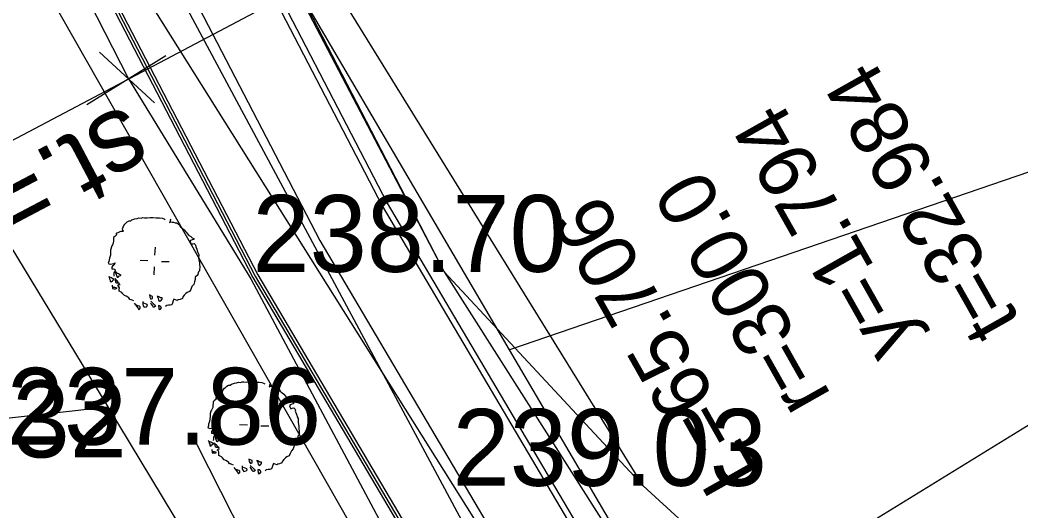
# Model space of a CAD drawing. Extents: x -601754 to -601440, y -1201912 to -1200862.
# Drawn here: x -601544.58 to -601518.53, y -1201354.54 to -1201341.75 of the extents above; entities that cross this region are included whole.
import ezdxf

# ---------------------------------------------------------------- set-up
doc = ezdxf.new("R2010")
doc.units = 0
for name, color, linetype in [('Hranice parcel', 7, 'Continuous'), ('u_drén', 7, 'Continuous'), ('u_hrany', 7, 'Continuous'), ('u_krizky', 7, 'Continuous'), ('u_návrh', 7, 'Continuous'), ('u_oblouky', 7, 'Continuous'), ('u_osa', 7, 'Continuous'), ('u_pricne_cesta', 7, 'Continuous'), ('u_terénní úpravy', 7, 'Continuous'), ('u_vysadba_SO_101', 7, 'Continuous'), ('u_vyska', 7, 'Continuous')]:
    doc.layers.add(name, color=color, linetype=linetype)

msp = doc.modelspace()

# ---------------------------------------------------------------- linework, layer by layer
at = {"layer": 'Hranice parcel'}
for p, q in [((-601697.78, -1201369.54), (-601542.3, -1201351.82)), ((-601542.3, -1201351.82), (-601532.14, -1201368.61))]:
    msp.add_line(p, q, dxfattribs=at)
for points in [[(-601531.84, -1201350.34), (-601539.52, -1201337.25), (-601549.44, -1201315.65)], [(-601555.49, -1201328.67), (-601550, -1201339.12), (-601542.3, -1201351.82)], [(-601508.86, -1201342.47), (-601512.53, -1201343.73), (-601531.84, -1201350.34)], [(-601514.66, -1201382.62), (-601516.09, -1201378.41), (-601518.22, -1201373.55), (-601531.84, -1201350.34)]]:
    msp.add_lwpolyline(points, dxfattribs=at)
at = {"layer": 'u_drén'}
msp.add_lwpolyline([(-601553.194, -1201317.864), (-601552.875, -1201318.687), (-601546.074, -1201333.752), (-601538.46, -1201348.424), (-601530.069, -1201362.635), (-601525.78, -1201369.465), (-601523.226, -1201373.891), (-601521.024, -1201378.462), (-601519.169, -1201383.184), (-601517.66, -1201388.066), (-601516.532, -1201392.263), (-601515.324, -1201397.601), (-601514.551, -1201402.98), (-601514.21, -1201408.403), (-601514.303, -1201413.875), (-601516.032, -1201444.23), (-601516.195, -1201450.215), (-601516.005, -1201456.227), (-601515.463, -1201462.19), (-601510.248, -1201505.371), (-601509.825, -1201509.657), (-601509.591, -1201513.936), (-601509.544, -1201518.242), (-601509.788, -1201540.615)], dxfattribs=at)
at = {"layer": 'u_hrany'}
for points in [[(-601564.55, -1201274.22), (-601554.98, -1201301.75), (-601550.1, -1201315.28), (-601544.95, -1201324.64), (-601539.81, -1201336.34), (-601533.54, -1201348.31)], [(-601563.01, -1201293.69), (-601544.18, -1201340.47), (-601528.42, -1201368.16), (-601520.9, -1201374.92)], [(-601528.36, -1201353.88), (-601539.51, -1201335.83), (-601544.47, -1201324.44)], [(-601520.9, -1201374.92), (-601531.36, -1201358), (-601541.87, -1201338.39)], [(-601533.54, -1201348.31), (-601528.36, -1201353.88), (-601525.06, -1201356.91)], [(-601520.9, -1201374.92), (-601531.08, -1201370.35), (-601539.97, -1201352.81)]]:
    msp.add_lwpolyline(points, dxfattribs=at)
at = {"layer": 'u_krizky'}
for p, q in [((-601540.791, -1201342.686), (-601542.843, -1201343.966)), ((-601541.084, -1201343.913), (-601542.51, -1201342.593))]:
    msp.add_line(p, q, dxfattribs=at)
at = {"layer": 'u_návrh'}
for points in [[(-601563.542, -1201278.368), (-601555.153, -1201301.929), (-601549.253, -1201317.17), (-601542.541, -1201332.04), (-601535.025, -1201346.521), (-601526.716, -1201360.593), (-601522.417, -1201367.44), (-601519.753, -1201372.056), (-601517.425, -1201376.89), (-601515.462, -1201381.885), (-601513.889, -1201386.977), (-601512.721, -1201391.321), (-601511.461, -1201396.888), (-601510.644, -1201402.577), (-601510.283, -1201408.313), (-601510.38, -1201414.02), (-601512.11, -1201444.395)], [(-601567.28, -1201279.795), (-601558.903, -1201303.323), (-601552.944, -1201318.716), (-601546.141, -1201333.785), (-601538.525, -1201348.46), (-601530.133, -1201362.674), (-601525.844, -1201369.504), (-601523.292, -1201373.926), (-601521.093, -1201378.492), (-601519.24, -1201383.209), (-601517.732, -1201388.087), (-601516.605, -1201392.281), (-601515.398, -1201397.615), (-601514.626, -1201402.988), (-601514.285, -1201408.405), (-601514.378, -1201413.873), (-601516.107, -1201444.227)], [(-601549.753, -1201316.295), (-601549.392, -1201317.228), (-601542.676, -1201332.105), (-601535.157, -1201346.594), (-601526.844, -1201360.671), (-601522.546, -1201367.518), (-601519.886, -1201372.126), (-601517.562, -1201376.951), (-601515.604, -1201381.935), (-601514.033, -1201387.018), (-601512.867, -1201391.357), (-601511.609, -1201396.915), (-601510.793, -1201402.592), (-601510.433, -1201408.317), (-601510.53, -1201414.015), (-601512.26, -1201444.389), (-601512.419, -1201450.207), (-601512.236, -1201455.996), (-601511.709, -1201461.793), (-601506.495, -1201504.959), (-601506.06, -1201509.368), (-601505.817, -1201513.812), (-601505.769, -1201518.242), (-601506.187, -1201556.503)], [(-601553.136, -1201317.803), (-601552.806, -1201318.658), (-601546.006, -1201333.72), (-601538.394, -1201348.388), (-601530.005, -1201362.596), (-601525.716, -1201369.427), (-601523.16, -1201373.856), (-601520.956, -1201378.432), (-601519.098, -1201383.159), (-601517.588, -1201388.045), (-601516.46, -1201392.245), (-601515.25, -1201397.587), (-601514.477, -1201402.972), (-601514.135, -1201408.402), (-601514.228, -1201413.878), (-601515.957, -1201444.233), (-601516.12, -1201450.215), (-601515.93, -1201456.223), (-601515.388, -1201462.182), (-601510.174, -1201505.363), (-601509.75, -1201509.651), (-601509.516, -1201513.934), (-601509.469, -1201518.242), (-601509.714, -1201540.624)]]:
    msp.add_lwpolyline(points, dxfattribs=at)
at = {"layer": 'u_oblouky'}
msp.add_line((-601528.425, -1201361.634), (-601545.965, -1201333.7), dxfattribs=at)
at = {"layer": 'u_osa'}
msp.add_lwpolyline([(-601557.028, -1201302.626), (-601551.099, -1201317.943), (-601544.341, -1201332.912), (-601536.775, -1201347.491), (-601528.425, -1201361.634), (-601524.131, -1201368.472), (-601521.523, -1201372.991), (-601519.259, -1201377.691), (-601517.351, -1201382.547), (-601515.811, -1201387.532), (-601514.663, -1201391.801), (-601513.43, -1201397.251), (-601512.635, -1201402.782), (-601512.284, -1201408.359), (-601512.379, -1201413.946), (-601514.108, -1201444.311)], dxfattribs=at)
at = {"layer": 'u_pricne_cesta'}
for points in [[(-601521.874, -1201332.787), (-601539.559, -1201342.128), (-601557.243, -1201351.468)], [(-601512.743, -1201348.863), (-601529.774, -1201359.348), (-601546.805, -1201369.834)]]:
    msp.add_lwpolyline(points, dxfattribs=at)
at = {"layer": 'u_terénní úpravy'}
for points in [[(-601563.549, -1201276.755), (-601560.467, -1201285.585), (-601555.466, -1201299.915), (-601555, -1201301.25), (-601553.702, -1201304.613), (-601549.711, -1201315.986), (-601546.008, -1201323.122), (-601539.52, -1201337.25), (-601537.344, -1201340.958), (-601533.54, -1201348.31), (-601527.44, -1201357.911), (-601522.351, -1201366.758), (-601519.36, -1201371.808), (-601517.434, -1201375.343), (-601516.299, -1201378.722), (-601515.181, -1201381.785), (-601513.502, -1201386.766), (-601512.274, -1201391.071), (-601511.36, -1201394.458), (-601510.891, -1201396.937), (-601510.105, -1201401.304), (-601509.884, -1201408.41), (-601509.865, -1201414.917), (-601511.161, -1201434.926)], [(-601565.037, -1201287.212), (-601558.145, -1201306.245), (-601553.368, -1201318.894), (-601550.549, -1201325.146), (-601546.519, -1201333.968), (-601541.758, -1201343.289), (-601538.578, -1201348.49), (-601532.041, -1201360.744), (-601526.088, -1201369.629), (-601523.664, -1201374.122), (-601522.125, -1201377.501), (-601519.788, -1201383.401), (-601518.29, -1201388.248), (-601517.27, -1201392.04), (-601516.455, -1201395.572), (-601515.96, -1201398.024), (-601515.065, -1201403.029), (-601514.933, -1201414.628), (-601514.933, -1201414.628), (-601516.331, -1201434.631)]]:
    msp.add_lwpolyline(points, dxfattribs=at)
at = {"layer": 'u_vysadba_SO_101'}
for points in [[(-601542.07, -1201347.331), (-601542.069, -1201347.302), (-601542.009, -1201347.276), (-601541.979, -1201347.263), (-601541.949, -1201347.25), (-601541.92, -1201347.251), (-601541.89, -1201347.253), (-601541.903, -1201347.223), (-601541.916, -1201347.193), (-601541.9, -1201347.15), (-601541.883, -1201347.107), (-601541.851, -1201347.065), (-601541.82, -1201347.037), (-601541.79, -1201347.009), (-601541.744, -1201346.983), (-601541.7, -1201346.985), (-601541.67, -1201346.957), (-601541.595, -1201346.932), (-601541.536, -1201346.92), (-601541.491, -1201346.908), (-601541.433, -1201346.911), (-601541.388, -1201346.899), (-601541.345, -1201346.901), (-601541.272, -1201346.905), (-601541.198, -1201346.894), (-601541.125, -1201346.898), (-601541.037, -1201346.903), (-601540.95, -1201346.907), (-601540.877, -1201346.911), (-601540.834, -1201346.928), (-601540.805, -1201346.944)], [(-601540.658, -1201346.937), (-601540.674, -1201346.966), (-601540.676, -1201346.995), (-601540.692, -1201347.023), (-601540.648, -1201347.011), (-601540.618, -1201347.013), (-601540.589, -1201347.014), (-601540.546, -1201347.031), (-601540.502, -1201347.033), (-601540.46, -1201347.065), (-601540.432, -1201347.096), (-601540.406, -1201347.141), (-601540.363, -1201347.173), (-601540.307, -1201347.22), (-601540.266, -1201347.266), (-601540.238, -1201347.296), (-601540.197, -1201347.357), (-601540.14, -1201347.389), (-601540.098, -1201347.421), (-601540.055, -1201347.438), (-601540.057, -1201347.467)], [(-601542.07, -1201347.331), (-601542.071, -1201347.346), (-601542.117, -1201347.387), (-601542.148, -1201347.415), (-601542.15, -1201347.459), (-601542.152, -1201347.503), (-601542.156, -1201347.561), (-601542.172, -1201347.604), (-601542.189, -1201347.633), (-601542.205, -1201347.661), (-601542.222, -1201347.719), (-601542.224, -1201347.748), (-601542.227, -1201347.806), (-601542.229, -1201347.85), (-601542.231, -1201347.879), (-601542.249, -1201347.952), (-601542.266, -1201347.995), (-601542.269, -1201348.038), (-601542.285, -1201348.067), (-601542.272, -1201348.097), (-601542.229, -1201348.114), (-601542.14, -1201348.089), (-601542.11, -1201348.076), (-601542.142, -1201348.133), (-601542.173, -1201348.161), (-601542.189, -1201348.189), (-601542.191, -1201348.233), (-601542.162, -1201348.234), (-601542.118, -1201348.237), (-601542.105, -1201348.267), (-601542.122, -1201348.31), (-601542.138, -1201348.338), (-601542.14, -1201348.382), (-601542.143, -1201348.426)], [(-601541.071, -1201347.873), (-601541.06, -1201347.668)], [(-601540.057, -1201347.467), (-601540.101, -1201347.479), (-601540.146, -1201347.492), (-601540.162, -1201347.52), (-601540.149, -1201347.55), (-601540.122, -1201347.595), (-601540.092, -1201347.582), (-601540.047, -1201347.57), (-601540.02, -1201347.601), (-601540.007, -1201347.631), (-601540.008, -1201347.66), (-601539.982, -1201347.72), (-601539.97, -1201347.764), (-601539.958, -1201347.809), (-601539.931, -1201347.854), (-601539.932, -1201347.884), (-601539.935, -1201347.927), (-601539.936, -1201347.957), (-601539.924, -1201348.001), (-601539.912, -1201348.06), (-601539.915, -1201348.119), (-601539.904, -1201348.178), (-601539.905, -1201348.207), (-601539.907, -1201348.236), (-601539.909, -1201348.28), (-601539.94, -1201348.308), (-601539.942, -1201348.337), (-601539.958, -1201348.38), (-601539.975, -1201348.408), (-601540.021, -1201348.45), (-601540.024, -1201348.508), (-601540.042, -1201348.566), (-601540.06, -1201348.638), (-601540.107, -1201348.694), (-601540.14, -1201348.766), (-601540.172, -1201348.823), (-601540.232, -1201348.849), (-601540.263, -1201348.876), (-601540.309, -1201348.918), (-601540.341, -1201348.96), (-601540.357, -1201349.003), (-601540.417, -1201349.029), (-601540.462, -1201349.042), (-601540.492, -1201349.055), (-601540.535, -1201349.038), (-601540.578, -1201349.021), (-601540.595, -1201349.064), (-601540.613, -1201349.122), (-601540.63, -1201349.165), (-601540.674, -1201349.177), (-601540.718, -1201349.175)], [(-601541.254, -1201348.024), (-601541.459, -1201348.013)], [(-601541.087, -1201348.18), (-601541.098, -1201348.384)], [(-601540.904, -1201348.043), (-601540.699, -1201348.039)], [(-601542.274, -1201348.419), (-601542.261, -1201348.449), (-601542.249, -1201348.493), (-601542.236, -1201348.523), (-601542.237, -1201348.553), (-601542.209, -1201348.569), (-601542.178, -1201348.541), (-601542.132, -1201348.5), (-601542.161, -1201348.498), (-601542.203, -1201348.466), (-601542.246, -1201348.45)], [(-601542.092, -1201348.297), (-601542.094, -1201348.34), (-601542.081, -1201348.37), (-601542.069, -1201348.415), (-601542.056, -1201348.445), (-601542.027, -1201348.446), (-601542.01, -1201348.418), (-601541.951, -1201348.392), (-601541.994, -1201348.375), (-601542.022, -1201348.359), (-601542.079, -1201348.327)], [(-601542.184, -1201348.658), (-601542.174, -1201348.746), (-601542.13, -1201348.749), (-601542.101, -1201348.75), (-601542.057, -1201348.738), (-601542.114, -1201348.72), (-601542.158, -1201348.718), (-601542.171, -1201348.688)], [(-601542.117, -1201348.486), (-601542.075, -1201348.532), (-601542.034, -1201348.578), (-601541.991, -1201348.609)], [(-601541.991, -1201348.609), (-601542.02, -1201348.608), (-601542.05, -1201348.606), (-601542.079, -1201348.605), (-601542.092, -1201348.575), (-601542.09, -1201348.546), (-601542.103, -1201348.516)], [(-601541.62, -1201349.068), (-601541.663, -1201349.051), (-601541.692, -1201349.035), (-601541.721, -1201349.034), (-601541.748, -1201348.988), (-601541.776, -1201348.972), (-601541.818, -1201348.941), (-601541.861, -1201348.924), (-601541.903, -1201348.878), (-601541.931, -1201348.847), (-601542.002, -1201348.814), (-601542, -1201348.77), (-601541.997, -1201348.726), (-601542.011, -1201348.696), (-601542.039, -1201348.68), (-601542.007, -1201348.638), (-601541.978, -1201348.639)], [(-601541.216, -1201348.899), (-601541.205, -1201348.973), (-601541.178, -1201349.018), (-601541.134, -1201349.006), (-601541.132, -1201348.977), (-601541.131, -1201348.948), (-601541.174, -1201348.931), (-601541.202, -1201348.915)], [(-601541.013, -1201348.939), (-601540.987, -1201348.999), (-601540.975, -1201349.044), (-601540.947, -1201349.075), (-601540.917, -1201349.062), (-601540.885, -1201349.019), (-601540.884, -1201348.99), (-601540.928, -1201348.988), (-601540.956, -1201348.972), (-601540.985, -1201348.955), (-601541.014, -1201348.954)], [(-601541.609, -1201349.127), (-601541.513, -1201349.25), (-601541.486, -1201349.295), (-601541.454, -1201349.253), (-601541.453, -1201349.224), (-601541.481, -1201349.207), (-601541.524, -1201349.191), (-601541.553, -1201349.174), (-601541.581, -1201349.158)], [(-601541.387, -1201349.081), (-601541.39, -1201349.154), (-601541.378, -1201349.198), (-601541.35, -1201349.229), (-601541.291, -1201349.217), (-601541.261, -1201349.19), (-601541.274, -1201349.16), (-601541.317, -1201349.143), (-601541.36, -1201349.126)], [(-601541.181, -1201349.077), (-601541.098, -1201349.154), (-601541.069, -1201349.171), (-601541.056, -1201349.201), (-601541.087, -1201349.228), (-601541.116, -1201349.227), (-601541.129, -1201349.197), (-601541.156, -1201349.151), (-601541.184, -1201349.121)], [(-601540.982, -1201349.19), (-601540.972, -1201349.264), (-601540.959, -1201349.294), (-601540.929, -1201349.281), (-601540.897, -1201349.238), (-601540.925, -1201349.208), (-601540.953, -1201349.191), (-601540.982, -1201349.19)], [(-601540.718, -1201349.175), (-601540.763, -1201349.187), (-601540.793, -1201349.215)], [(-601539.479, -1201351.608), (-601539.478, -1201351.578), (-601539.418, -1201351.552), (-601539.388, -1201351.539), (-601539.358, -1201351.526), (-601539.329, -1201351.528), (-601539.299, -1201351.529), (-601539.312, -1201351.499), (-601539.325, -1201351.469), (-601539.309, -1201351.426), (-601539.292, -1201351.383), (-601539.26, -1201351.341), (-601539.229, -1201351.313), (-601539.199, -1201351.286), (-601539.153, -1201351.259), (-601539.109, -1201351.261), (-601539.079, -1201351.233), (-601539.004, -1201351.208), (-601538.945, -1201351.197), (-601538.9, -1201351.184), (-601538.842, -1201351.187), (-601538.797, -1201351.175), (-601538.754, -1201351.177), (-601538.681, -1201351.181), (-601538.607, -1201351.171), (-601538.534, -1201351.174), (-601538.446, -1201351.179), (-601538.359, -1201351.184), (-601538.286, -1201351.188), (-601538.243, -1201351.204), (-601538.214, -1201351.221)], [(-601538.067, -1201351.214), (-601538.083, -1201351.242), (-601538.085, -1201351.271), (-601538.101, -1201351.3), (-601538.057, -1201351.287), (-601538.027, -1201351.289), (-601537.998, -1201351.291), (-601537.955, -1201351.307), (-601537.911, -1201351.31), (-601537.869, -1201351.341), (-601537.841, -1201351.372), (-601537.815, -1201351.417), (-601537.772, -1201351.449), (-601537.716, -1201351.496), (-601537.675, -1201351.542), (-601537.647, -1201351.573), (-601537.606, -1201351.633), (-601537.549, -1201351.666), (-601537.507, -1201351.697), (-601537.464, -1201351.714), (-601537.466, -1201351.743)], [(-601539.479, -1201351.608), (-601539.48, -1201351.622), (-601539.526, -1201351.664), (-601539.557, -1201351.691), (-601539.559, -1201351.735), (-601539.561, -1201351.779), (-601539.565, -1201351.837), (-601539.581, -1201351.88), (-601539.598, -1201351.909), (-601539.614, -1201351.937), (-601539.631, -1201351.995), (-601539.633, -1201352.024), (-601539.636, -1201352.083), (-601539.638, -1201352.126), (-601539.64, -1201352.156), (-601539.658, -1201352.228), (-601539.675, -1201352.271), (-601539.678, -1201352.315), (-601539.694, -1201352.343), (-601539.681, -1201352.373), (-601539.638, -1201352.39), (-601539.549, -1201352.365), (-601539.519, -1201352.352), (-601539.551, -1201352.409), (-601539.582, -1201352.437), (-601539.598, -1201352.465), (-601539.6, -1201352.509), (-601539.571, -1201352.511), (-601539.527, -1201352.513), (-601539.514, -1201352.543), (-601539.531, -1201352.586), (-601539.547, -1201352.614), (-601539.549, -1201352.658), (-601539.552, -1201352.702)], [(-601537.466, -1201351.743), (-601537.51, -1201351.756), (-601537.555, -1201351.768), (-601537.571, -1201351.796), (-601537.558, -1201351.826), (-601537.531, -1201351.872), (-601537.501, -1201351.859), (-601537.456, -1201351.846), (-601537.429, -1201351.877), (-601537.416, -1201351.907), (-601537.417, -1201351.936), (-601537.391, -1201351.996), (-601537.379, -1201352.041), (-601537.367, -1201352.085), (-601537.34, -1201352.131), (-601537.341, -1201352.16), (-601537.344, -1201352.204), (-601537.345, -1201352.233), (-601537.333, -1201352.277), (-601537.321, -1201352.337), (-601537.324, -1201352.395), (-601537.313, -1201352.454), (-601537.314, -1201352.483), (-601537.316, -1201352.513), (-601537.318, -1201352.556), (-601537.349, -1201352.584), (-601537.351, -1201352.613), (-601537.367, -1201352.656), (-601537.384, -1201352.685), (-601537.43, -1201352.726), (-601537.433, -1201352.785), (-601537.451, -1201352.842), (-601537.469, -1201352.915), (-601537.516, -1201352.971), (-601537.549, -1201353.042), (-601537.581, -1201353.099), (-601537.641, -1201353.125), (-601537.672, -1201353.153), (-601537.718, -1201353.194), (-601537.75, -1201353.237), (-601537.766, -1201353.28), (-601537.826, -1201353.306), (-601537.871, -1201353.318), (-601537.901, -1201353.331), (-601537.944, -1201353.314), (-601537.987, -1201353.297), (-601538.004, -1201353.34), (-601538.022, -1201353.398), (-601538.039, -1201353.441), (-601538.083, -1201353.453), (-601538.127, -1201353.451)], [(-601538.48, -1201352.149), (-601538.469, -1201351.945)], [(-601538.663, -1201352.301), (-601538.868, -1201352.29)], [(-601538.313, -1201352.319), (-601538.108, -1201352.315)], [(-601539.501, -1201352.573), (-601539.503, -1201352.617), (-601539.49, -1201352.647), (-601539.478, -1201352.691), (-601539.465, -1201352.721), (-601539.436, -1201352.723), (-601539.419, -1201352.694), (-601539.36, -1201352.668), (-601539.403, -1201352.651), (-601539.431, -1201352.635), (-601539.488, -1201352.603)], [(-601538.496, -1201352.456), (-601538.507, -1201352.66)], [(-601539.683, -1201352.695), (-601539.67, -1201352.725), (-601539.658, -1201352.77), (-601539.645, -1201352.8), (-601539.646, -1201352.829), (-601539.618, -1201352.845), (-601539.587, -1201352.817), (-601539.541, -1201352.776), (-601539.57, -1201352.774), (-601539.612, -1201352.743), (-601539.655, -1201352.726)], [(-601539.526, -1201352.762), (-601539.484, -1201352.808), (-601539.443, -1201352.854), (-601539.4, -1201352.886)], [(-601539.4, -1201352.886), (-601539.429, -1201352.884), (-601539.459, -1201352.883), (-601539.488, -1201352.881), (-601539.501, -1201352.851), (-601539.499, -1201352.822), (-601539.512, -1201352.792)], [(-601539.593, -1201352.934), (-601539.583, -1201353.022), (-601539.539, -1201353.025), (-601539.51, -1201353.026), (-601539.466, -1201353.014), (-601539.523, -1201352.996), (-601539.567, -1201352.994), (-601539.58, -1201352.964)], [(-601539.029, -1201353.345), (-601539.072, -1201353.328), (-601539.101, -1201353.312), (-601539.13, -1201353.31), (-601539.157, -1201353.265), (-601539.185, -1201353.249), (-601539.227, -1201353.217), (-601539.27, -1201353.2), (-601539.312, -1201353.154), (-601539.34, -1201353.123), (-601539.411, -1201353.09), (-601539.409, -1201353.046), (-601539.406, -1201353.003), (-601539.42, -1201352.973), (-601539.448, -1201352.956), (-601539.416, -1201352.914), (-601539.387, -1201352.916)], [(-601539.018, -1201353.404), (-601538.922, -1201353.526), (-601538.895, -1201353.571), (-601538.863, -1201353.529), (-601538.862, -1201353.5), (-601538.89, -1201353.484), (-601538.933, -1201353.467), (-601538.962, -1201353.451), (-601538.99, -1201353.435)], [(-601538.796, -1201353.357), (-601538.799, -1201353.43), (-601538.787, -1201353.475), (-601538.759, -1201353.505), (-601538.7, -1201353.494), (-601538.67, -1201353.466), (-601538.683, -1201353.436), (-601538.726, -1201353.419), (-601538.769, -1201353.402)], [(-601538.625, -1201353.176), (-601538.614, -1201353.249), (-601538.587, -1201353.295), (-601538.543, -1201353.282), (-601538.541, -1201353.253), (-601538.54, -1201353.224), (-601538.583, -1201353.207), (-601538.611, -1201353.191)], [(-601538.59, -1201353.353), (-601538.507, -1201353.431), (-601538.478, -1201353.447), (-601538.465, -1201353.477), (-601538.496, -1201353.505), (-601538.525, -1201353.503), (-601538.538, -1201353.473), (-601538.565, -1201353.428), (-601538.593, -1201353.397)], [(-601538.422, -1201353.216), (-601538.396, -1201353.276), (-601538.384, -1201353.32), (-601538.356, -1201353.351), (-601538.326, -1201353.338), (-601538.294, -1201353.296), (-601538.293, -1201353.266), (-601538.337, -1201353.264), (-601538.365, -1201353.248), (-601538.394, -1201353.232), (-601538.423, -1201353.23)], [(-601538.391, -1201353.466), (-601538.381, -1201353.54), (-601538.368, -1201353.57), (-601538.338, -1201353.557), (-601538.306, -1201353.515), (-601538.334, -1201353.484), (-601538.362, -1201353.468), (-601538.391, -1201353.466)], [(-601538.127, -1201353.451), (-601538.172, -1201353.463), (-601538.202, -1201353.491)]]:
    msp.add_lwpolyline(points, dxfattribs=at)

# ---------------------------------------------------------------- texts
at = {"layer": 'u_oblouky'}
for s, p in [('t=32.984', (-601518.523, -1201349.586)), ('y=1.794', (-601521.247, -1201350.1)), ('r=300.0', (-601523.455, -1201351.529)), ('L=65.706', (-601525.325, -1201353.555))]:
    msp.add_text(s, height=1.5, rotation=119.4465, dxfattribs=at).set_placement(p)
at = {"layer": 'u_pricne_cesta'}
msp.add_text('st.=0.51827', height=2, rotation=207.8415, dxfattribs=at).set_placement((-601541.834, -1201343.926))
at = {"layer": 'u_vyska'}
for s, p in [('238.70', (-601538.532, -1201348.31)), ('237.86', (-601544.926, -1201352.81)), ('237.32', (-601549.981, -1201353.14)), ('239.03', (-601533.322, -1201353.88))]:
    msp.add_text(s, height=2, dxfattribs=at).set_placement(p)

doc.saveas('drawing.dxf')
